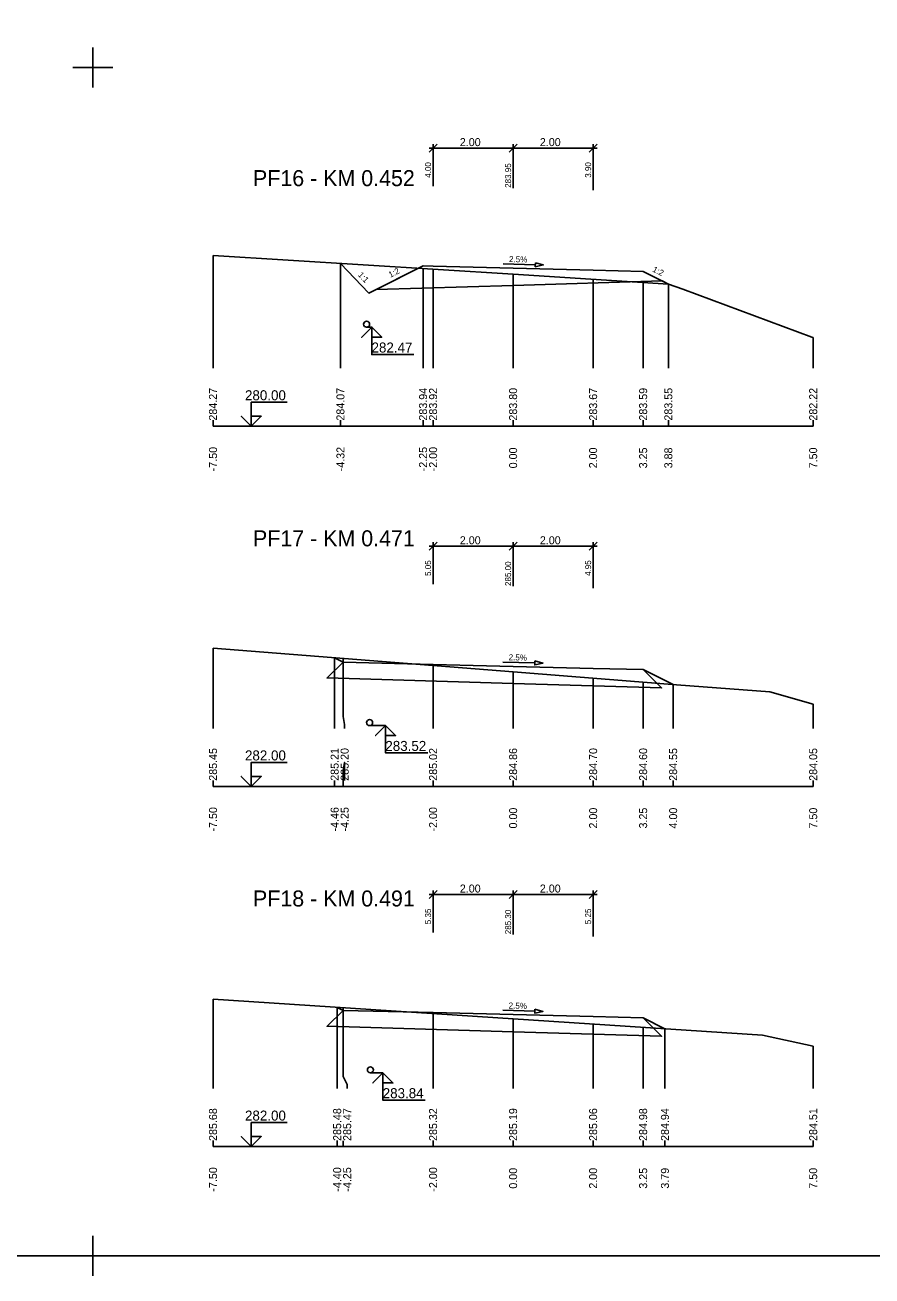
# Model space of a CAD drawing. Extents: x -5 to 1895, y -2 to 602.
# Drawn here: x 1033 to 1244.7, y -2.3 to 310.3 of the extents above; entities that cross this region are included whole.
import ezdxf

# ---------------------------------------------------------------- set-up
doc = ezdxf.new("R2010")
doc.units = 0
for name, color, linetype in [('KOTA', 7, 'Continuous'), ('KOTA_DELKY', 7, 'Continuous'), ('KOTA_DELKY_CONT', 7, 'Continuous'), ('KRIZENI', 7, 'Continuous'), ('NS_TELESO_VOZOVKY', 7, 'Continuous'), ('NS_V_PF', 7, 'Continuous'), ('REZY_PF_PUVODNI', 7, 'Continuous'), ('SESTAVY_REZU_PF', 7, 'Continuous'), ('SKLON', 7, 'Continuous'), ('SVK', 7, 'Continuous')]:
    doc.layers.add(name, color=color, linetype=linetype)

msp = doc.modelspace()

# ---------------------------------------------------------------- linework, layer by layer
for p, q in [((1050, 304.67), (1050, 294.67)), ((1050, 304.67), (1050, 294.67)), ((1050, 304.67), (1050, 294.67)), ((1050, 304.67), (1050, 294.67)), ((1050, 304.67), (1050, 294.67)), ((1050, 304.67), (1050, 294.67)), ((1050, 304.67), (1050, 294.67)), ((1050, 304.67), (1050, 294.67)), ((1050, 304.67), (1050, 294.67)), ((1050, 304.67), (1050, 294.67)), ((1050, 304.67), (1050, 294.67)), ((1050, 304.67), (1050, 294.67)), ((1050, 304.67), (1050, 294.67)), ((1050, 304.67), (1050, 294.67)), ((1050, 304.67), (1050, 294.67)), ((1050, 304.67), (1050, 294.67)), ((1050, 304.67), (1050, 294.67)), ((1050, 304.67), (1050, 294.67)), ((1050, 304.67), (1050, 294.67)), ((1050, 304.67), (1050, 294.67)), ((1050, 304.67), (1050, 294.67)), ((1050, 304.67), (1050, 294.67)), ((1050, 304.67), (1050, 294.67)), ((1050, 304.67), (1050, 294.67)), ((1050, 304.67), (1050, 294.67)), ((1050, 304.67), (1050, 294.67)), ((1050, 304.67), (1050, 294.67)), ((1050, 304.67), (1050, 294.67)), ((1050, 304.67), (1050, 294.67)), ((1050, 304.67), (1050, 294.67)), ((1050, 304.67), (1050, 294.67)), ((1050, 304.67), (1050, 294.67)), ((1050, 304.67), (1050, 294.67)), ((1050, 304.67), (1050, 294.67)), ((1050, 304.67), (1050, 294.67)), ((1050, 304.67), (1050, 294.67)), ((1050, 304.67), (1050, 294.67)), ((1050, 304.67), (1050, 294.67)), ((1050, 304.67), (1050, 294.67)), ((1050, 304.67), (1050, 294.67)), ((1050, 304.67), (1050, 294.67)), ((1050, 304.67), (1050, 294.67)), ((1050, 304.67), (1050, 294.67)), ((1050, 304.67), (1050, 294.67)), ((1050, 304.67), (1050, 294.67)), ((1050, 304.67), (1050, 294.67)), ((1050, 304.67), (1050, 294.67)), ((1050, 304.67), (1050, 294.67)), ((1050, 304.67), (1050, 294.67)), ((1050, 304.67), (1050, 294.67)), ((1050, 304.67), (1050, 294.67)), ((1050, 304.67), (1050, 294.67)), ((1050, 304.67), (1050, 294.67)), ((1050, 304.67), (1050, 294.67)), ((1055, 299.67), (1045, 299.67)), ((1055, 299.67), (1045, 299.67)), ((1055, 299.67), (1045, 299.67)), ((1055, 299.67), (1045, 299.67)), ((1055, 299.67), (1045, 299.67)), ((1055, 299.67), (1045, 299.67)), ((1055, 299.67), (1045, 299.67)), ((1055, 299.67), (1045, 299.67)), ((1055, 299.67), (1045, 299.67)), ((1055, 299.67), (1045, 299.67)), ((1055, 299.67), (1045, 299.67)), ((1055, 299.67), (1045, 299.67)), ((1055, 299.67), (1045, 299.67)), ((1055, 299.67), (1045, 299.67)), ((1055, 299.67), (1045, 299.67)), ((1055, 299.67), (1045, 299.67)), ((1055, 299.67), (1045, 299.67)), ((1055, 299.67), (1045, 299.67)), ((1055, 299.67), (1045, 299.67)), ((1055, 299.67), (1045, 299.67)), ((1055, 299.67), (1045, 299.67)), ((1055, 299.67), (1045, 299.67)), ((1055, 299.67), (1045, 299.67)), ((1055, 299.67), (1045, 299.67)), ((1055, 299.67), (1045, 299.67)), ((1055, 299.67), (1045, 299.67)), ((1055, 299.67), (1045, 299.67)), ((1055, 299.67), (1045, 299.67)), ((1055, 299.67), (1045, 299.67)), ((1055, 299.67), (1045, 299.67)), ((1055, 299.67), (1045, 299.67)), ((1055, 299.67), (1045, 299.67)), ((1055, 299.67), (1045, 299.67)), ((1055, 299.67), (1045, 299.67)), ((1055, 299.67), (1045, 299.67)), ((1055, 299.67), (1045, 299.67)), ((1055, 299.67), (1045, 299.67)), ((1055, 299.67), (1045, 299.67)), ((1055, 299.67), (1045, 299.67)), ((1055, 299.67), (1045, 299.67)), ((1055, 299.67), (1045, 299.67)), ((1055, 299.67), (1045, 299.67)), ((1055, 299.67), (1045, 299.67)), ((1055, 299.67), (1045, 299.67)), ((1055, 299.67), (1045, 299.67)), ((1055, 299.67), (1045, 299.67)), ((1055, 299.67), (1045, 299.67)), ((1055, 299.67), (1045, 299.67)), ((1055, 299.67), (1045, 299.67)), ((1055, 299.67), (1045, 299.67)), ((1055, 299.67), (1045, 299.67)), ((1055, 299.67), (1045, 299.67)), ((1055, 299.67), (1045, 299.67)), ((1055, 299.67), (1045, 299.67)), ((1050, 7.67), (1050, -2.33)), ((1050, 7.67), (1050, -2.33)), ((1050, 7.67), (1050, -2.33)), ((1050, 7.67), (1050, -2.33)), ((1050, 7.67), (1050, -2.33)), ((1050, 7.67), (1050, -2.33)), ((1050, 7.67), (1050, -2.33)), ((1050, 7.67), (1050, -2.33)), ((1050, 7.67), (1050, -2.33)), ((1050, 7.67), (1050, -2.33)), ((1050, 7.67), (1050, -2.33)), ((1050, 7.67), (1050, -2.33)), ((1055, 2.67), (1045, 2.67)), ((1055, 2.67), (1045, 2.67)), ((1055, 2.67), (1045, 2.67)), ((1055, 2.67), (1045, 2.67)), ((1055, 2.67), (1045, 2.67)), ((1055, 2.67), (1045, 2.67)), ((1055, 2.67), (1045, 2.67)), ((1055, 2.67), (1045, 2.67)), ((1055, 2.67), (1045, 2.67)), ((1055, 2.67), (1045, 2.67)), ((1055, 2.67), (1045, 2.67)), ((1055, 2.67), (1045, 2.67))]:
    msp.add_line(p, q)
msp.add_lwpolyline([(0, 596.67), (1890, 596.67), (1890, 2.67), (0, 2.67)], close=True)
at = {"layer": 'KOTA'}
for points in [[(1119.66, 234.75), (1117.16, 232.25), (1119.66, 234.75), (1119.66, 227.93), (1130.2, 227.93)], [(1118.38, 234.75), (1119.74, 234.75)], [(1119.66, 234.75), (1122.16, 232.25), (1119.66, 232.25), (1119.66, 234.75)], [(1119.66, 234.75), (1122.16, 232.25), (1119.66, 232.25)], [(1089.57, 210), (1087.07, 212.5), (1089.57, 210), (1089.57, 216), (1098.57, 216)], [(1089.57, 210), (1092.07, 212.5), (1089.57, 212.5), (1089.57, 210)], [(1089.57, 210), (1092.07, 212.5), (1089.57, 212.5)], [(1119.13, 135.19), (1123.12, 135.19)], [(1123.12, 135.19), (1120.62, 132.69), (1123.12, 135.19), (1123.12, 128.37), (1133.66, 128.37)], [(1123.12, 135.19), (1125.62, 132.69), (1123.12, 132.69), (1123.12, 135.19)], [(1123.12, 135.19), (1125.62, 132.69), (1123.12, 132.69)], [(1089.57, 120), (1087.07, 122.5), (1089.57, 120), (1089.57, 126), (1098.57, 126)], [(1089.57, 120), (1092.07, 122.5), (1089.57, 122.5), (1089.57, 120)], [(1089.57, 120), (1092.07, 122.5), (1089.57, 122.5)], [(1119.32, 48.43), (1122.46, 48.43)], [(1122.46, 48.43), (1119.96, 45.93), (1122.46, 48.43), (1122.46, 41.6), (1133, 41.6)], [(1122.46, 48.43), (1124.96, 45.93), (1122.46, 45.93), (1122.46, 48.43)], [(1122.46, 48.43), (1124.96, 45.93), (1122.46, 45.93)], [(1089.57, 30), (1087.07, 32.5), (1089.57, 30), (1089.57, 36), (1098.57, 36)], [(1089.57, 30), (1092.07, 32.5), (1089.57, 32.5), (1089.57, 30)], [(1089.57, 30), (1092.07, 32.5), (1089.57, 32.5)]]:
    msp.add_lwpolyline(points, dxfattribs=at)
at = {"layer": 'KOTA_DELKY'}
for points in [[(1134, 278.51), (1136, 280.51)], [(1134, 279.51), (1156, 279.51)], [(1135, 270.01), (1135, 280.51)], [(1154, 278.51), (1156, 280.51)], [(1154, 278.51), (1156, 280.51)], [(1154, 279.51), (1176, 279.51)], [(1155, 269.51), (1155, 280.51)], [(1155, 269.51), (1155, 280.51)], [(1174, 278.51), (1176, 280.51)], [(1175, 269.01), (1175, 280.51)], [(1134, 179.01), (1136, 181.01)], [(1134, 180.01), (1156, 180.01)], [(1135, 170.51), (1135, 181.01)], [(1154, 179.01), (1156, 181.01)], [(1154, 179.01), (1156, 181.01)], [(1154, 180.01), (1176, 180.01)], [(1155, 170.01), (1155, 181.01)], [(1155, 170.01), (1155, 181.01)], [(1174, 179.01), (1176, 181.01)], [(1175, 169.51), (1175, 181.01)], [(1134, 91.98), (1136, 93.98)], [(1135, 83.48), (1135, 93.98)], [(1154, 91.98), (1156, 93.98)], [(1154, 91.98), (1156, 93.98)], [(1155, 82.98), (1155, 93.98)], [(1155, 82.98), (1155, 93.98)], [(1174, 91.98), (1176, 93.98)], [(1175, 82.48), (1175, 93.98)], [(1134, 92.98), (1156, 92.98)], [(1154, 92.98), (1176, 92.98)]]:
    msp.add_lwpolyline(points, dxfattribs=at)
at = {"layer": 'KRIZENI'}
for centre in [(1118.38, 235.5), (1119.13, 135.94), (1119.32, 49.18)]:
    msp.add_circle(centre, 0.75, dxfattribs=at)
at = {"layer": 'NS_TELESO_VOZOVKY'}
for points in [[(1155, 249.51), (1175, 249.01), (1187.5, 248.69), (1193.8, 245.54), (1192.24, 246.32), (1155, 245.21), (1120.78, 244.18), (1132.5, 250.07), (1135, 250.01), (1155, 249.51)], [(1155, 150.01), (1175, 149.51), (1187.5, 149.2), (1192.1, 144.6), (1155, 145.71), (1108.53, 147.11), (1112.5, 151.08), (1135, 150.51), (1155, 150.01)], [(1155, 62.98), (1175, 62.48), (1187.5, 62.17), (1192.1, 57.57), (1155, 58.68), (1108.53, 60.08), (1112.5, 64.04), (1135, 63.48), (1155, 62.98)]]:
    msp.add_lwpolyline(points, dxfattribs=at)
at = {"layer": 'NS_V_PF'}
for points in [[(1111.88, 250.68), (1118.97, 243.27), (1132.5, 250.07), (1135, 250.01), (1155, 249.51), (1175, 249.01), (1187.5, 248.69), (1193.8, 245.54)], [(1110.4, 152.13), (1112.5, 151.08), (1135, 150.51), (1155, 150.01), (1175, 149.51), (1187.5, 149.2), (1195, 145.45)], [(1111.03, 64.78), (1112.5, 64.04), (1135, 63.48), (1155, 62.98), (1175, 62.48), (1187.5, 62.17), (1192.95, 59.45)]]:
    msp.add_lwpolyline(points, dxfattribs=at)
at = {"layer": 'REZY_PF_PUVODNI'}
for points in [[(1080, 252.68), (1155, 247.98), (1193.87, 245.54), (1197.41, 244.25), (1229.63, 232.25), (1230, 232.19)], [(1080, 154.53), (1155, 148.61), (1195.84, 145.39), (1219.19, 143.63), (1230, 140.52)], [(1080, 66.8), (1155, 61.92), (1217.3, 57.86), (1230, 55.06)]]:
    msp.add_lwpolyline(points, dxfattribs=at)
at = {"layer": 'SESTAVY_REZU_PF'}
for points in [[(1080, 210), (1230, 210)], [(1080, 120), (1230, 120)], [(1080, 30), (1230, 30)]]:
    msp.add_lwpolyline(points, dxfattribs=at)
at = {"layer": 'SKLON'}
for points in [[(1152.55, 250.57), (1160.54, 250.37)], [(1160.56, 250.87), (1162.54, 250.32), (1160.53, 249.87), (1160.56, 250.87)], [(1152.45, 151.08), (1160.45, 150.88)], [(1160.46, 151.38), (1162.45, 150.83), (1160.43, 150.38), (1160.46, 151.38)], [(1152.45, 64.05), (1160.45, 63.85)], [(1160.46, 64.35), (1162.45, 63.8), (1160.43, 63.35), (1160.46, 64.35)]]:
    msp.add_lwpolyline(points, dxfattribs=at)
for points in [[(1160.56, 250.87), (1162.54, 250.32), (1160.53, 249.87)], [(1160.46, 151.38), (1162.45, 150.83), (1160.43, 150.38)], [(1160.46, 64.35), (1162.45, 63.8), (1160.43, 63.35)]]:
    msp.add_lwpolyline(points, close=True, dxfattribs=at)
at = {"layer": 'SVK'}
for points in [[(1080, 224.5), (1080, 252.68)], [(1111.85, 224.5), (1111.85, 250.69)], [(1132.5, 224.5), (1132.5, 249.39)], [(1135, 224.5), (1135, 249.23)], [(1155, 224.5), (1155, 247.98)], [(1175, 224.5), (1175, 246.72)], [(1187.5, 224.5), (1187.5, 245.94)], [(1193.8, 224.5), (1193.8, 245.54)], [(1230, 224.5), (1230, 232.19)], [(1080, 210), (1080, 211.5)], [(1111.85, 210), (1111.85, 211.5)], [(1132.5, 210), (1132.5, 211.5)], [(1135, 210), (1135, 211.5)], [(1155, 210), (1155, 211.5)], [(1175, 210), (1175, 211.5)], [(1187.5, 210), (1187.5, 211.5)], [(1193.8, 210), (1193.8, 211.5)], [(1230, 210), (1230, 211.5)], [(1080, 134.5), (1080, 154.53)], [(1110.4, 134.5), (1110.4, 152.13)], [(1112.9, 134.5), (1112.9, 135.5), (1112.5, 137.5), (1112.5, 151.96)], [(1135, 134.5), (1135, 150.19)], [(1155, 134.5), (1155, 148.61)], [(1175, 134.5), (1175, 147.03)], [(1187.5, 134.5), (1187.5, 146.04)], [(1195, 134.5), (1195, 145.45)], [(1230, 134.5), (1230, 140.52)], [(1112.5, 120), (1112.5, 124), (1112.9, 126), (1112.9, 121.5)], [(1080, 120), (1080, 121.5)], [(1110.4, 120), (1110.4, 121.5)], [(1135, 120), (1135, 121.5)], [(1155, 120), (1155, 121.5)], [(1175, 120), (1175, 121.5)], [(1187.5, 120), (1187.5, 121.5)], [(1195, 120), (1195, 121.5)], [(1230, 120), (1230, 121.5)], [(1080, 44.5), (1080, 66.8)], [(1111.03, 44.5), (1111.03, 64.78)], [(1113.53, 44.5), (1113.53, 45.5), (1112.55, 47.5), (1112.55, 64.68)], [(1135, 44.5), (1135, 63.22)], [(1155, 44.5), (1155, 61.92)], [(1175, 44.5), (1175, 60.61)], [(1187.5, 44.5), (1187.5, 59.8)], [(1192.95, 44.5), (1192.95, 59.45)], [(1230, 44.5), (1230, 55.06)], [(1080, 30), (1080, 31.5)], [(1111.03, 30), (1111.03, 31.5)], [(1112.53, 29.99), (1112.53, 31.35), (1112.53, 31.47), (1112.53, 31.47)], [(1135, 30), (1135, 31.5)], [(1155, 30), (1155, 31.5)], [(1175, 30), (1175, 31.5)], [(1187.5, 30), (1187.5, 31.5)], [(1192.95, 30), (1192.95, 31.5)], [(1230, 30), (1230, 31.5)]]:
    msp.add_lwpolyline(points, dxfattribs=at)

# ---------------------------------------------------------------- texts
at = {"layer": 'KOTA'}
for s, p in [('282.47', (1119.62, 228.43)), ('280.00', (1087.99, 216.5)), ('283.52', (1123.07, 128.87)), ('282.00', (1087.99, 126.5)), ('283.84', (1122.41, 42.1)), ('282.00', (1087.99, 36.5))]:
    msp.add_text(s, height=2.5, dxfattribs=at).set_placement(p)
at = {"layer": 'KOTA_DELKY'}
for p in [(1141.69, 280.01), (1161.69, 280.01), (1141.69, 180.51), (1161.69, 180.51), (1141.69, 93.48), (1161.69, 93.48)]:
    msp.add_text('2.00', height=2, dxfattribs=at).set_placement(p)
at = {"layer": 'KOTA_DELKY_CONT'}
for s, p in [('4.00', (1134.5, 272.1)), ('283.95', (1154.5, 269.58)), ('3.90', (1174.5, 272.1)), ('5.05', (1134.5, 172.6)), ('285.00', (1154.5, 170.09)), ('4.95', (1174.5, 172.6)), ('5.35', (1134.5, 85.57)), ('285.30', (1154.5, 83.06)), ('5.25', (1174.5, 85.57))]:
    msp.add_text(s, height=1.5, rotation=90, dxfattribs=at).set_placement(p)
at = {"layer": 'SESTAVY_REZU_PF'}
for s, p in [('PF16 - KM 0.452', (1090, 270)), ('PF17 - KM 0.471', (1090, 180)), ('PF18 - KM 0.491', (1090, 90))]:
    msp.add_text(s, height=4, dxfattribs=at).set_placement(p)
at = {"layer": 'SKLON'}
for s, rotation, p in [('2.5%', 358.5679, (1153.97, 251.03)), ('1:1', 313.6939, (1116.11, 247.71)), ('1:2', 26.6859, (1124.32, 247.08)), ('1:2', 333.4349, (1189.69, 248.72)), ('2.5%', 358.5679, (1153.87, 151.54)), ('2.5%', 358.5679, (1153.87, 64.51))]:
    msp.add_text(s, height=1.5, rotation=rotation, dxfattribs=at).set_placement(p)
at = {"layer": 'SVK'}
for s, p in [(' 284.27', (1081, 210.67)), (' 284.07', (1112.85, 210.67)), (' 283.94', (1133.5, 210.67)), (' 283.92', (1136, 210.67)), (' 283.80', (1156, 210.67)), (' 283.67', (1176, 210.67)), (' 283.59', (1188.5, 210.67)), (' 283.55', (1194.8, 210.67)), (' 282.22', (1231, 210.67)), (' -7.50', (1081, 198)), (' -4.32', (1112.85, 198)), (' -2.25', (1133.5, 198)), (' -2.00', (1136, 198)), ('  0.00', (1156, 198)), ('  2.00', (1176, 198)), ('  3.25', (1188.5, 198)), ('  3.88', (1194.8, 198)), ('  7.50', (1231, 198)), (' 285.45', (1081, 120.67)), (' 285.21', (1111.4, 120.67)), (' 285.20', (1113.9, 120.67)), (' 285.02', (1136, 120.67)), (' 284.86', (1156, 120.67)), (' 284.70', (1176, 120.67)), (' 284.60', (1188.5, 120.67)), (' 284.55', (1196, 120.67)), (' 284.05', (1231, 120.67)), (' -7.50', (1081, 108)), (' -4.46', (1111.4, 108)), (' -4.25', (1113.9, 108)), (' -2.00', (1136, 108)), ('  0.00', (1156, 108)), ('  2.00', (1176, 108)), ('  3.25', (1188.5, 108)), ('  4.00', (1196, 108)), ('  7.50', (1231, 108)), (' 285.68', (1081, 30.67)), (' 285.48', (1112.03, 30.67)), (' 285.47', (1114.53, 30.67)), (' 285.32', (1136, 30.67)), (' 285.19', (1156, 30.67)), (' 285.06', (1176, 30.67)), (' 284.98', (1188.5, 30.67)), (' 284.94', (1193.95, 30.67)), (' 284.51', (1231, 30.67)), (' -7.50', (1081, 18)), (' -4.40', (1112.03, 18)), (' -4.25', (1114.53, 18)), (' -2.00', (1136, 18)), ('  0.00', (1156, 18)), ('  2.00', (1176, 18)), ('  3.25', (1188.5, 18)), ('  3.79', (1193.95, 18)), ('  7.50', (1231, 18))]:
    msp.add_text(s, height=2, rotation=90, dxfattribs=at).set_placement(p)

doc.saveas('drawing.dxf')
